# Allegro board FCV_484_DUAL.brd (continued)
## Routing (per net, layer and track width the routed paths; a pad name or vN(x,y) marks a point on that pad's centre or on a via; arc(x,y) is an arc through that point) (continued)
IO-BANK4_6: length 7
  TOP w0.076: 164.41,171.17 165.21,171.17 165.34,171.29 165.79,171.29 165.98,171.09 165.98,170.89 166.22,170.65 167,170.65 167.08,170.57 v1(167.59,170.57)
  TOP w0.127: U1.J4 v1(167.59,170.57)
  SIG1 w0.076: v1(167.59,170.57) 164.79,170.57
IO-BANK4_7: length 4.4
  TOP w0.127: U1.J6 v1(169.19,170.57)
  SIG2 w0.076: v1(169.19,170.57) 168.78,170.98 165.48,170.98
IO-BANK4_8: length 5.9
  TOP w0.127: U1.J7 v1(169.99,170.57)
  SIG1 w0.076: v1(169.99,170.57) 169.6,170.18 164.77,170.18
IO-BANK4_9: length 7.9
  TOP w0.127: U1.J8 v1(170.79,170.57)
  SIG2 w0.076: v1(170.79,170.57) 170.41,170.95 170.41,171.63 170.31,171.74 169.86,171.74 169.58,172.02 169.58,172.37 169.35,172.59 164.92,172.59
IO-BANK4_10: length 9.6
  TOP w0.127: U1.J9 v1(171.59,170.57)
  SIG2 w0.076: v1(171.59,170.57) 171.99,170.97 173.61,170.97 173.95,171.32 173.95,177.7
IO-BANK4_11: length 1.2
  TOP w0.076: U1.K1 164.39,169.37
IO-BANK4_12: length 2.9
  TOP w0.127: U1.K3 v1(166.79,169.77)
  SIG1 w0.076: 164.58,169.41 166.43,169.41 v1(166.79,169.77)
IO-BANK4_13: length 3.8
  TOP w0.127: U1.K4 v1(167.59,169.77)
  SIG1 w0.076: 164.58,169.17 166.81,169.17 167.42,169.77 v1(167.59,169.77)
IO-BANK4_14: length 4.7
  TOP w0.127: U1.K5 v1(168.39,169.77)
  SIG1 w0.076: v1(168.39,169.77) 167.99,169.37 167.38,169.37 166.91,168.91 164.58,168.91
IO-BANK4_15: length 5.7
  TOP w0.127: U1.K6 v1(169.19,169.77)
  SIG1 w0.076: 164.58,168.61 167.98,168.61 169.14,169.77 v1(169.19,169.77)
IO-BANK4_16: length 6.5
  TOP w0.127: U1.K8 v1(170.79,169.77)
  SIG2 w0.076: v1(170.79,169.77) 170.38,170.19 165.01,170.19
IO-BANK4_17: length 7.4
  TOP w0.127: U1.K9 v1(171.59,169.77)
  SIG2 w0.076: 164.96,169.36 171.18,169.36 v1(171.59,169.77)
IO-BANK4_18: length 1.2
  TOP w0.076: U1.L1 164.39,168.57
IO-BANK4_19: length 2.1
  TOP w0.076: U1.L2 166.07,168.9 164.39,168.9
IO-BANK4_20: length 3
  TOP w0.076: 164.4,169.05 166.71,169.05 U1.L3
IO-BANK4_21: length 4.6
  TOP w0.076: 164.4,168.36 165.13,168.36 165.23,168.26 165.84,168.26 165.95,168.15 168.37,168.15 U1.L5
IO-BANK4_22: length 5.4
  TOP w0.127: U1.L6 v1(169.19,168.97)
  SIG1 w0.076: 164.58,168.39 168.61,168.39 v1(169.19,168.97)
IO-BANK4_23: length 6.3
  TOP w0.127: U1.L7 v1(169.99,168.97)
  SIG1 w0.076: 164.58,168.18 169.2,168.18 v1(169.99,168.97)
IO-BANK4_24: length 6.5
  TOP w0.127: U1.L8 v1(170.79,168.97)
  SIG2 w0.076: v1(170.79,168.97) 170.35,168.53 165,168.53
IO-BANK4_25: length 2.2
  TOP w0.076: 164.36,168.16 165,168.16 165.07,168.09 165.75,168.09 166.07,167.77 U1.M2
IO-BANK4_26: length 3
  TOP w0.076: U1.M3 166.88,167.46 165.05,167.46 164.98,167.38 164.34,167.38
IO-BANK4_27: length 3.9
  TOP w0.076: U1.M4 167.52,167.31 165.3,167.31 165.15,167.16 164.36,167.16
IO-BANK4_28: length 4.5
  TOP w0.127: U1.M5 v1(168.39,167.37)
  SIG1 w0.076: 164.61,166.97 165.77,166.97 166.17,167.37 v1(168.39,167.37)
IO-BANK4_29: length 6.3
  TOP w0.127: U1.M7 v1(169.99,167.37)
  SIG1 w0.076: 164.61,167.17 165.69,167.17 166.25,167.73 169.63,167.73 v1(169.99,167.37)
IO-BANK4_30: length 7.2
  TOP w0.127: U1.M8 v1(170.79,167.37)
  SIG1 w0.076: v1(170.79,167.37) 170.2,167.97 166.11,167.97 165.52,167.38 164.63,167.38
IO-BANK4_31: length 8.7
  TOP w0.127: U1.M9 v1(171.59,167.37)
  SIG2 w0.076: 164.56,167.23 165.11,167.23 166.11,168.23 171.26,168.23 171.59,167.91 v1(171.59,167.37)
IO-BANK4_32: length 1.2
  TOP w0.076: U1.N1 164.39,166.97
IO-BANK4_33: length 2.1
  TOP w0.076: 164.39,166.66 166.08,166.66 U1.N2
IO-BANK4_34: length 3.9
  TOP w0.127: U1.N4 v1(167.59,166.57)
  SIG1 w0.076: v1(167.59,166.57) 167.43,166.57 167.08,166.92 166.39,166.92 166,166.54 164.59,166.54
IO-BANK4_35: length 4.8
  TOP w0.127: U1.N5 v1(168.39,166.57)
  SIG1 w0.076: 164.59,166.76 165.87,166.76 166.26,167.14 167.18,167.14 167.35,166.97 167.99,166.97 v1(168.39,166.57)
IO-BANK4_36: length 5.3
  TOP w0.127: U1.N6 v1(169.19,166.57)
  SIG1 w0.076: 164.65,166.15 168.74,166.15 169.16,166.57 v1(169.19,166.57)
IO-BANK4_37: length 6.3
  TOP w0.127: U1.N7 v1(169.99,166.57)
  SIG2 w0.076: 164.68,166.35 165.77,166.35 166.41,166.99 169.57,166.99 v1(169.99,166.57)
IO-BANK4_38: length 8.1
  TOP w0.127: U1.N8 v1(170.79,166.57)
  SIG2 w0.076: 164.6,166.84 165.65,166.84 166.72,167.92 170.06,167.92 170.37,167.61 170.37,167 v1(170.79,166.57)
IO-BANK4_39: length 1.2
  TOP w0.076: U1.P1 164.39,166.17
IO-BANK4_40: length 2.1
  TOP w0.076: U1.P2 166.06,166.5 164.39,166.5
IO-BANK4_41: length 2.9
  TOP w0.076: 164.4,165.86 166.52,165.86 166.62,165.96 166.98,165.96 U1.P3
IO-BANK4_42: length 3.8
  TOP w0.076: 164.38,165.71 166.59,165.71 166.65,165.77 167.59,165.77 U1.P4
IO-BANK4_43: length 5.4
  TOP w0.127: U1.P6 v1(169.19,165.77)
  SIG1 w0.076: v1(169.19,165.77) 168.78,165.36 167.85,165.36 167.35,165.86 164.69,165.86
IO-BANK4_44: length 6
  TOP w0.127: U1.P7 v1(169.99,165.77)
  SIG2 w0.076: v1(169.99,165.77) 169.6,165.38 164.71,165.38
IO-BANK4_45: length 6.9
  TOP w0.127: U1.P8 v1(170.79,165.77)
  SIG2 w0.076: 164.83,165.8 167.7,165.8 168.07,166.17 170.39,166.17 v1(170.79,165.77)
IO-BANK4_46: length 7.6
  TOP w0.127: U1.P9 v1(171.59,165.77)
  SIG2 w0.076: v1(171.59,165.77) 171.96,165.4 171.96,158.88
IO-BANK4_47: length 1.2
  TOP w0.076: U1.R1 164.39,165.37
IO-BANK4_48: length 2.9
  TOP w0.127: U1.R3 v1(166.79,164.97)
  SIG1 w0.076: 164.69,165.43 166.33,165.43 v1(166.79,164.97)
IO-BANK4_49: length 3.7
  TOP w0.127: U1.R4 v1(167.59,164.97)
  SIG1 w0.076: 164.69,165.62 166.94,165.62 v1(167.59,164.97)
IO-BANK4_50: length 4.3
  TOP w0.127: U1.R5 v1(168.39,164.97)
  SIG1 w0.076: v1(168.39,164.97) 168.01,164.59 164.77,164.59
IO-BANK4_51: length 5.2
  TOP w0.127: U1.R6 v1(169.19,164.97)
  SIG2 w0.076: 164.74,164.55 168.58,164.55 169,164.97 v1(169.19,164.97)
IO-BANK4_52: length 8.5
  TOP w0.127: U1.R8 v1(170.79,164.97)
  SIG2 w0.076: 168.77,158.69 168.77,164.32 169.04,164.59 170.41,164.59 v1(170.79,164.97)
IO-BANK4_53: length 1.2
  TOP w0.076: U1.T1 164.39,164.57
IO-BANK4_54: length 2.1
  TOP w0.076: U1.T2 166.08,164.26 165.33,164.26 165.21,164.38 164.44,164.38
IO-BANK4_55: length 3
  TOP w0.076: U1.T3 166.72,164.11 165.19,164.11 165.13,164.17 164.44,164.17
IO-BANK4_56: length 4.8
  TOP w0.127: U1.T5 v1(168.39,164.17)
  SIG1 w0.076: v1(168.39,164.17) 168.01,163.79 165.74,163.79 165.22,163.27 164.54,163.27
IO-BANK5_1: length 1.2
  TOP w0.076: U1.D1 164.39,174.17
IO-BANK5_2: length 2.1
  TOP w0.076: 164.39,174.49 165.78,174.49 166.09,174.17 U1.D2
IO-BANK5_3: length 1.2
  TOP w0.076: U1.E1 164.39,173.37
IO-BANK5_4: length 3.6
  TOP w0.076: 164.41,174.66 165.9,174.66 166.07,174.49 166.6,174.49 166.77,174.32 166.77,173.79 U1.E3
IO-BANK5_5: length 1.2
  TOP w0.076: U1.F1 164.39,172.57
IO-BANK5_6: length 2.1
  TOP w0.076: 164.39,172.89 166.07,172.89 U1.F2
IO-BANK5_7: length 3
  TOP w0.076: 164.38,173.04 166.72,173.04 U1.F3
IO-BANK5_8: length 4.3
  TOP w0.127: U1.F5 v1(168.39,172.97)
  SIG1 w0.076: v1(168.39,172.97) 168.01,173.35 164.81,173.35
IO-BANK5_9: length 2.2
  TOP w0.076: 164.4,172.17 165.14,172.17 165.21,172.11 166.06,172.11 U1.G2
IO-BANK5_10: length 3
  TOP w0.076: U1.G3 166.71,172.26 165.32,172.26 165.21,172.37 164.43,172.37
IO-BANK5_11: length 3.4
  TOP w0.127: U1.G4 v1(167.59,172.17)
  SIG1 w0.076: v1(167.59,172.17) 167.46,172.31 164.86,172.31
IO-BANK5_12: length 4.2
  TOP w0.127: U1.G5 v1(168.39,172.17)
  SIG1 w0.076: 164.87,172.56 168,172.56 v1(168.39,172.17)
JTAG-IO_1: length 5.8
  TOP w0.127: U1.F6 v1(169.19,172.97)
  SIG1 w0.076: 164.98,174.56 167.78,174.56 168.16,174.18 168.59,174.18 168.76,174 168.76,173.37 169.15,172.97 v1(169.19,172.97)
JTAG-IO_2: length 5.8
  TOP w0.127: U1.F7 v1(169.99,172.97)
  SIG1 w0.076: 169.75,177.96 169.75,174.91 169.58,174.74 169.58,173.38 v1(169.99,172.97)
JTAG-IO_3: length 5.6
  TOP w0.127: U1.F8 v1(170.79,172.97)
  SIG1 w0.076: v1(170.79,172.97) 171.16,173.35 171.16,174.77 171.47,175.07 171.47,177.76
JTAG-IO_4: length 5.4
  TOP w0.127: U1.G7 v1(169.99,172.17)
  SIG2 w0.076: 169.59,176.88 169.59,172.78 169.99,172.37 v1(169.99,172.17)
JTAG-IO_5: length 6.6
  TOP w0.127: U1.G8 v1(170.79,172.17)
  SIG2 w0.076: 170.35,178.01 170.35,172.61 v1(170.79,172.17)
JTAG-IO_6: length 6.4
  TOP w0.127: U1.G9 v1(171.59,172.17)
  SIG2 w0.076: 171.22,177.87 171.22,172.54 v1(171.59,172.17)
JTAG-IO_7: length 6.2
  TOP w0.127: U1.G10 v1(172.39,172.17)
  SIG2 w0.076: 172.78,177.67 172.78,172.57 v1(172.39,172.17)
JTAG-IO_8: length 3
  TOP w0.127: U1.H4 v1(167.59,171.37)
  SIG1 w0.076: v1(167.59,171.37) 167.2,171.76 165.31,171.76
JTAG-IO_9: length 4.2
  TOP w0.127: U1.H5 v1(168.39,171.37)
  SIG1 w0.076: 164.9,170.98 168,170.98 v1(168.39,171.37)
JTAG-IO_10: length 4.7
  TOP w0.127: U1.H6 v1(169.19,171.37)
  SIG1 w0.076: 165.36,172.07 167.16,172.07 167.47,171.76 168.8,171.76 v1(169.19,171.37)
JTAG-IO_11: length 6.1
  TOP w0.127: U1.H7 v1(169.99,171.37)
  SIG2 w0.076: v1(169.99,171.37) 169.8,171.37 169.42,171.75 166.3,171.75 165.87,171.32 164.78,171.32
JTAG-IO_12: length 5.9
  TOP w0.127: U1.H9 v1(171.59,171.37)
  SIG2 w0.076: 171.99,176.58 171.99,171.78 v1(171.59,171.37)
JTAG-IO_13: length 7.8
  TOP w0.127: U1.H10 v1(172.39,171.37)
  SIG2 w0.076: v1(172.39,171.37) 172.8,171.78 173.47,171.78 173.63,171.94 173.63,177.74
REFCLK0_1: length 3.8
  TOP w0.076: 183.5,167.62 182.9,167.62 182.72,167.44 180.46,167.44 U1.N19
REFCLK0_2: length 2.9
  TOP w0.076: 183.5,167.43 183.04,167.43 182.9,167.29 181.1,167.29 U1.N20
REFCLK1_1: length 4
  TOP w0.127: U1.L19 v1(180.39,168.97)
  SIG1 w0.076: 183.43,169.16 182.73,169.16 182.1,168.54 180.83,168.54 v1(180.39,168.97)
REFCLK1_2: length 3
  TOP w0.076: U1.L20 v1(181.19,168.97)
  SIG1 w0.076: v1(181.19,168.97) 181.63,169.41 183.44,169.41
REFCLK2_1: length 3.8
  TOP w0.127: U1.J19 v1(180.39,170.57)
  SIG1 w0.076: 183.48,170.99 180.81,170.99 v1(180.39,170.57)
REFCLK2_2: length 3.2
  TOP w0.127: U1.J20 v1(181.19,170.57)
  SIG1 w0.076: 183.43,170.7 182.71,170.7 182.17,170.16 181.6,170.16 v1(181.19,170.57)
RX0_1: length 3.9
  TOP w0.127: U1.R19 v1(180.39,164.97)
  SIG1 w0.076: 183.56,164.56 180.8,164.56 v1(180.39,164.97)
RX0_2: length 3.2
  TOP w0.127: U1.R20 v1(181.19,164.97)
  SIG1 w0.076: v1(181.19,164.97) 181.6,165.38 182.16,165.38 182.63,164.91 183.46,164.91
RX1_1: length 2.1
  TOP w0.076: 183.53,168.15 181.96,168.15 U1.M21
RX1_2: length 1.1
  TOP w0.076: U1.M22 182.51,167.9 183.48,167.9
RX2_1: length 2.3
  TOP w0.076: U1.K21 181.99,169.77 183.69,169.77
RX2_2: length 1.3
  TOP w0.076: U1.K22 183.7,169.37
RX3_1: length 3.9
  TOP w0.127: U1.G19 v1(180.39,172.17)
  SIG1 w0.076: 183.6,172.58 180.79,172.58 v1(180.39,172.17)
RX3_2: length 3.4
  TOP w0.127: U1.G20 v1(181.19,172.17)
  SIG1 w0.076: v1(181.19,172.17) 181.61,171.75 182.36,171.75 182.75,172.14 183.72,172.14
SERDES_VREF: length 1.1
  TOP w0.381: U1.H18 v1(179.59,171.37) ; U1.H19 v1(180.39,171.37)
TX0_1: length 2.1
  TOP w0.076: 183.57,164.18 181.98,164.18 U1.T21
TX0_2: length 1.1
  TOP w0.076: U1.T22 183.48,164.57
TX1_1: length 2.2
  TOP w0.076: U1.P21 181.98,165.78 183.64,165.78
TX1_2: length 1.1
  TOP w0.076: U1.P22 183.51,166.17
TX2_1: length 2.2
  TOP w0.076: U1.H21 181.98,171.36 183.64,171.36
TX2_2: length 1.3
  TOP w0.076: U1.H22 183.7,170.97
TX3_1: length 2.3
  TOP w0.076: 183.77,172.97 181.99,172.97 U1.F21
TX3_2: length 1.4
  TOP w0.076: U1.F22 183.8,172.57
